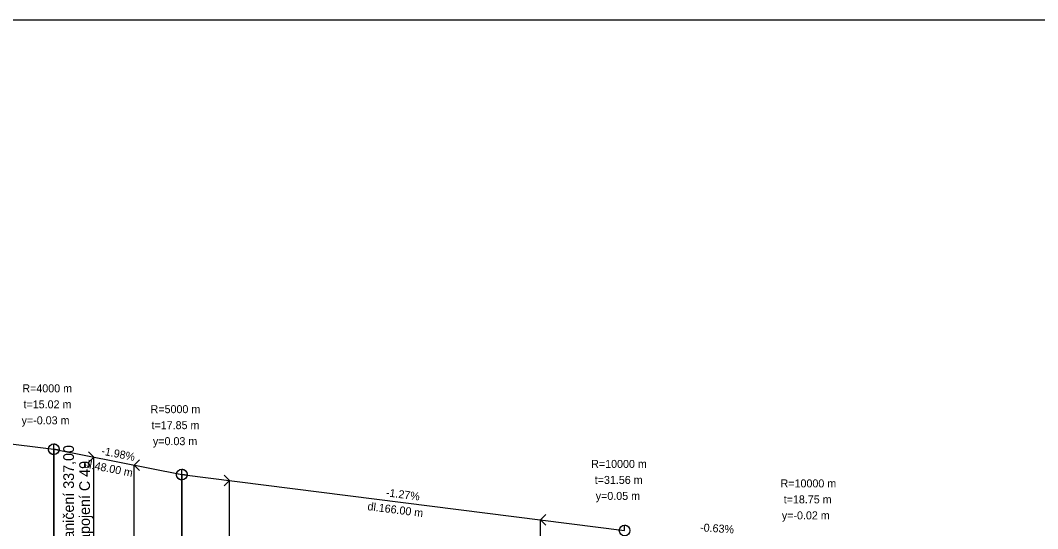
# Model space of a CAD drawing. Extents: x -550605 to -538780, y -1102367 to -1093705.
# Drawn here: x -541084.3 to -540703, y -1097298 to -1097107.3 of the extents above; entities that cross this region are included whole.
import ezdxf

# ---------------------------------------------------------------- set-up
doc = ezdxf.new("R2010")
doc.units = 0
for name, color, linetype in [('PP - objekty', 7, 'Continuous'), ('PP - popis', 7, 'Continuous'), ('Vrstva 57 - Ohrada pro tisk', 7, 'Continuous')]:
    doc.layers.add(name, color=color, linetype=linetype)

msp = doc.modelspace()

# ---------------------------------------------------------------- linework, layer by layer
at = {"layer": 'PP - popis'}
for p, q in [((-541128.8, -1097261.16), (-541071.8, -1097268.16)), ((-541071.8, -1097268.16), (-541023.8, -1097277.66)), ((-541071.8, -1097368.16), (-541071.8, -1097268.16)), ((-541071.8, -1097268.16), (-541071.8, -1097512.53)), ((-541056.78, -1097371.13), (-541056.78, -1097271.13)), ((-541041.65, -1097374.13), (-541041.65, -1097274.13)), ((-541023.8, -1097277.66), (-540857.8, -1097298.66)), ((-541023.8, -1097377.66), (-541023.8, -1097277.66)), ((-541023.8, -1097277.66), (-541023.8, -1097512.53)), ((-541005.95, -1097379.92), (-541005.95, -1097279.92)), ((-540889.36, -1097394.67), (-540889.36, -1097294.67))]:
    msp.add_line(p, q, dxfattribs=at)
for points in [[(-541071.8, -1097268.16), (-541071.8, -1097266.16), (-541071.67, -1097266.16), (-541071.54, -1097266.18), (-541071.42, -1097266.2), (-541071.29, -1097266.22), (-541071.17, -1097266.26), (-541071.05, -1097266.3), (-541070.93, -1097266.36), (-541070.82, -1097266.42), (-541070.71, -1097266.48), (-541070.6, -1097266.56), (-541070.5, -1097266.64), (-541070.41, -1097266.72), (-541070.32, -1097266.81), (-541070.23, -1097266.91), (-541070.16, -1097267.01), (-541070.09, -1097267.12), (-541070.02, -1097267.23), (-541069.97, -1097267.35), (-541069.92, -1097267.47), (-541069.88, -1097267.59), (-541069.85, -1097267.71), (-541069.82, -1097267.84), (-541069.81, -1097267.97), (-541069.8, -1097268.09), (-541069.8, -1097268.22), (-541069.81, -1097268.35), (-541069.82, -1097268.48), (-541069.84, -1097268.55), (-541071.8, -1097268.16), (-541071.8, -1097270.16), (-541071.93, -1097270.15), (-541072.05, -1097270.14), (-541072.18, -1097270.12), (-541072.31, -1097270.09), (-541072.43, -1097270.06), (-541072.55, -1097270.01), (-541072.67, -1097269.96), (-541072.78, -1097269.9), (-541072.89, -1097269.83), (-541072.99, -1097269.76), (-541073.09, -1097269.68), (-541073.19, -1097269.6), (-541073.28, -1097269.5), (-541073.36, -1097269.41), (-541073.44, -1097269.3), (-541073.51, -1097269.2), (-541073.57, -1097269.08), (-541073.63, -1097268.97), (-541073.67, -1097268.85), (-541073.72, -1097268.73), (-541073.75, -1097268.6), (-541073.77, -1097268.48), (-541073.79, -1097268.35), (-541073.8, -1097268.22), (-541073.8, -1097268.09), (-541073.79, -1097267.97), (-541073.78, -1097267.91)], [(-541023.8, -1097277.66), (-541023.8, -1097275.66), (-541023.67, -1097275.66), (-541023.54, -1097275.68), (-541023.42, -1097275.7), (-541023.29, -1097275.72), (-541023.17, -1097275.76), (-541023.05, -1097275.8), (-541022.93, -1097275.86), (-541022.82, -1097275.92), (-541022.71, -1097275.98), (-541022.6, -1097276.06), (-541022.5, -1097276.14), (-541022.41, -1097276.22), (-541022.32, -1097276.31), (-541022.23, -1097276.41), (-541022.16, -1097276.51), (-541022.09, -1097276.62), (-541022.02, -1097276.73), (-541021.97, -1097276.85), (-541021.92, -1097276.97), (-541021.88, -1097277.09), (-541021.85, -1097277.21), (-541021.82, -1097277.34), (-541021.81, -1097277.47), (-541021.8, -1097277.59), (-541021.8, -1097277.72), (-541021.81, -1097277.85), (-541021.81, -1097277.91), (-541023.8, -1097277.66), (-541023.8, -1097279.66), (-541023.93, -1097279.65), (-541024.05, -1097279.64), (-541024.18, -1097279.62), (-541024.31, -1097279.59), (-541024.43, -1097279.56), (-541024.55, -1097279.51), (-541024.67, -1097279.46), (-541024.78, -1097279.4), (-541024.89, -1097279.33), (-541024.99, -1097279.26), (-541025.09, -1097279.18), (-541025.19, -1097279.1), (-541025.28, -1097279), (-541025.36, -1097278.91), (-541025.44, -1097278.8), (-541025.51, -1097278.7), (-541025.57, -1097278.58), (-541025.63, -1097278.47), (-541025.67, -1097278.35), (-541025.72, -1097278.23), (-541025.75, -1097278.1), (-541025.77, -1097277.98), (-541025.79, -1097277.85), (-541025.8, -1097277.72), (-541025.8, -1097277.59), (-541025.79, -1097277.47), (-541025.77, -1097277.34), (-541025.76, -1097277.27)]]:
    msp.add_lwpolyline(points, close=True, dxfattribs=at)
for points in [[(-541058.78, -1097269.13), (-541056.78, -1097271.13), (-541058.78, -1097273.13)], [(-541039.65, -1097272.13), (-541041.65, -1097274.13), (-541039.65, -1097276.13)], [(-541007.95, -1097277.92), (-541005.95, -1097279.92), (-541007.95, -1097281.92)], [(-540887.36, -1097292.67), (-540889.36, -1097294.67), (-540887.36, -1097296.67)], [(-540857.8, -1097298.66), (-540857.8, -1097296.66), (-540857.67, -1097296.66), (-540857.54, -1097296.68), (-540857.42, -1097296.7), (-540857.29, -1097296.72), (-540857.17, -1097296.76), (-540857.05, -1097296.8), (-540856.93, -1097296.86), (-540856.82, -1097296.92), (-540856.71, -1097296.98), (-540856.6, -1097297.06), (-540856.5, -1097297.14), (-540856.41, -1097297.22), (-540856.32, -1097297.31), (-540856.23, -1097297.41), (-540856.16, -1097297.51), (-540856.09, -1097297.62), (-540856.02, -1097297.73), (-540855.97, -1097297.85), (-540855.92, -1097297.97)]]:
    msp.add_lwpolyline(points, dxfattribs=at)
for centre in [(-541071.8, -1097268.16), (-541023.8, -1097277.66), (-540857.8, -1097298.66)]:
    msp.add_circle(centre, 2, dxfattribs=at)
at = {"layer": 'Vrstva 57 - Ohrada pro tisk'}
msp.add_lwpolyline([(-541634.97, -1097677.25), (-538779.82, -1097677.25), (-538779.81, -1097107.25), (-541634.97, -1097107.25)], close=True, dxfattribs=at)

# ---------------------------------------------------------------- texts
at = {"layer": 'PP - objekty'}
for s, p in [('Staničení 337,00', (-541064.25, -1097306.76)), ('Napojení C 49', (-541058.25, -1097306.76))]:
    msp.add_text(s, height=4, rotation=90, dxfattribs=at).set_placement(p)
at = {"layer": 'PP - popis'}
for s, p in [('R=4000 m', (-541083.58, -1097246.81)), ('t=15.02 m', (-541083.15, -1097252.81)), ('R=5000 m', (-541035.51, -1097254.63)), ('y=-0.03 m', (-541083.87, -1097258.81)), ('t=17.85 m', (-541035.17, -1097260.63)), ('y=0.03 m', (-541034.64, -1097266.63)), ('R=10000 m', (-540870.35, -1097275.17)), ('t=31.56 m', (-540869.02, -1097281.17)), ('R=10000 m', (-540799.35, -1097282.47)), ('y=0.05 m', (-540868.64, -1097287.17)), ('t=18.75 m', (-540798.17, -1097288.47)), ('y=-0.02 m', (-540798.87, -1097294.47))]:
    msp.add_text(s, height=3, dxfattribs=at).set_placement(p)
for s, rotation, p in [('-1.98%', 348.8049, (-541054.15, -1097270.12)), ('dl.48.00 m', 348.8049, (-541060.86, -1097274.91)), ('-1.27%', 352.79, (-540947.41, -1097285.81)), ('dl.166.00 m', 352.79, (-540954.32, -1097290.98)), ('-0.63%', 356.3734, (-540829.59, -1097298.94))]:
    msp.add_text(s, height=3, rotation=rotation, dxfattribs=at).set_placement(p)

doc.saveas('drawing.dxf')
